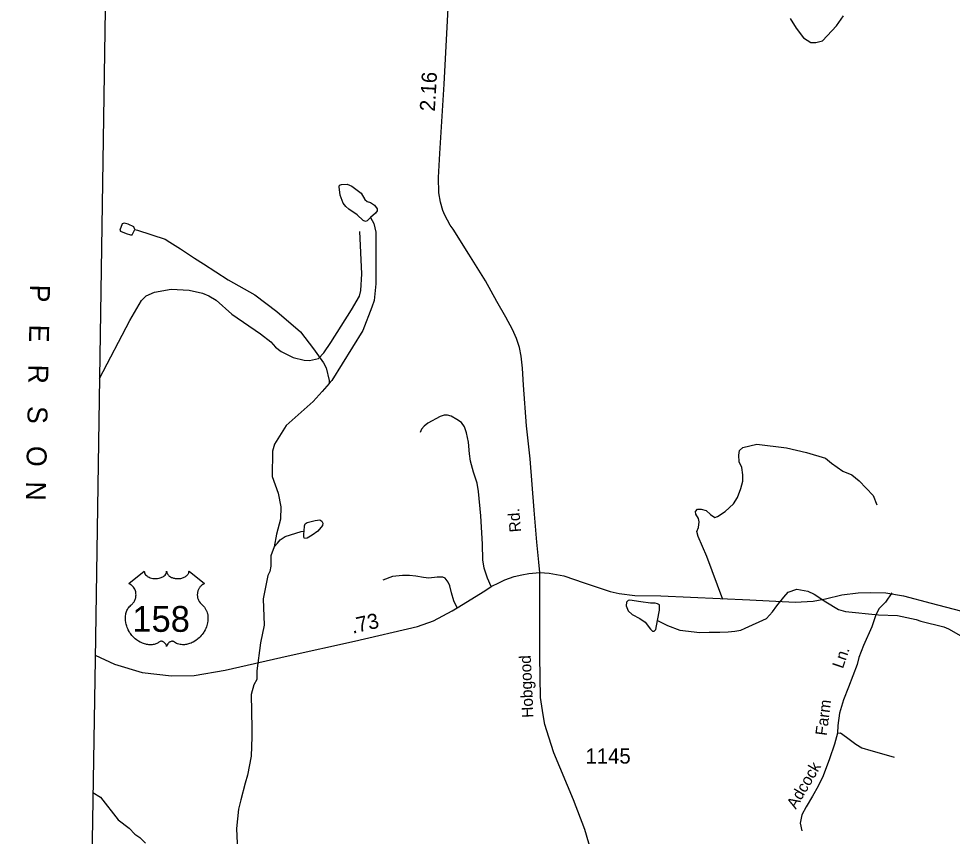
# Model space of a CAD drawing. Extents: x 2056842 to 2160602, y 826753 to 1016856.
# Drawn here: x 2058297 to 2065985, y 938922 to 945656 of the extents above; entities that cross this region are included whole.
import ezdxf

# ---------------------------------------------------------------- set-up
doc = ezdxf.new("R2010")
doc.units = 0
for name, color, linetype in [('Exist Boundary Political CountyLine', 7, 'Continuous'), ('Exist Boundary Political CountyLine Label', 7, 'Continuous'), ('Exist Hydrographic Misc Water Feature', 7, 'Continuous'), ('Exist Hydrographic River Shore', 7, 'Continuous'), ('Exist Road Non-System Type 51', 7, 'Continuous'), ('Exist Road Non-System Type 51 Label', 7, 'Continuous'), ('Exist Road Primary US Attributed', 7, 'Continuous'), ('Exist Road Primary US Mileage Hundredths English Label', 7, 'Continuous'), ('Exist Road Primary US Shield CELL', 7, 'Continuous'), ('Exist Road Primary US Shield Number Label', 7, 'Continuous'), ('Exist Road Secondary Mileage Hundredths English Label', 7, 'Continuous'), ('Exist Road Secondary Type 51 Attributed', 7, 'Continuous'), ('Exist Road Secondary Type 51 Label', 7, 'Continuous'), ('Exist Road Secondary Type 51 Number Label', 7, 'Continuous')]:
    doc.layers.add(name, color=color, linetype=linetype)

msp = doc.modelspace()

# ---------------------------------------------------------------- linework, layer by layer
at = {"layer": 'Exist Boundary Political CountyLine'}
msp.add_lwpolyline([(2059856.6, 1016190.3), (2059992.1, 1014583.5), (2060287.9, 1010619.4), (2060242.2, 1008370.9), (2060207.5, 1006770.5), (2060178.3, 1005306.3), (2060151, 1003993.9), (2060126.7, 1003051.7), (2060085.9, 1001469.5), (2060082.6, 1001042.9), (2059970.1, 996247.2), (2059900.3, 992964.9), (2059780.5, 986400.7), (2059706.7, 983126.5), (2059583, 976558.1), (2059387.4, 966719.6), (2059309.7, 963431.4), (2059197.6, 956451.1), (2059161.2, 955539), (2058926.7, 940379.5), (2058724.8, 928102.2), (2058408.1, 910016.3), (2058297.2, 904795.7)], dxfattribs=at)
at = {"layer": 'Exist Hydrographic Misc Water Feature'}
for points in [[(2061194.4, 944018.4), (2061165.4, 943989.4), (2061153.8, 943985), (2061135, 943993.7), (2061084.3, 944040.1), (2061016.2, 944088), (2060990.1, 944108.3), (2060968.4, 944137.3), (2060943.7, 944201.1), (2060936.5, 944272.1), (2060939.4, 944285.1), (2060955.3, 944290.9), (2061003.1, 944292.4), (2061040.8, 944275), (2061116.1, 944218.5), (2061148, 944167.7), (2061165.4, 944150.3), (2061192.9, 944141.6), (2061226.3, 944118.4), (2061248, 944090.9), (2061249.4, 944072), (2061234.9, 944053.2), (2061194.4, 944018.4)], [(2061194.4, 944018.4), (2061222.5, 943968.1), (2061238.5, 943896.2), (2061239.3, 943472.1), (2061223.5, 943334.1), (2061205.7, 943280.1), (2061130, 943087.9), (2060876.8, 942675.5), (2060852.8, 942651.4)], [(2059198.4, 943962.4), (2059166.4, 943970.3), (2059150.5, 943966.3), (2059130.6, 943914.2), (2059134.7, 943906.2), (2059182.6, 943886.3)], [(2059182.6, 943886.3), (2059218.7, 943874.4), (2059230.6, 943874.4), (2059254.6, 943918.5)], [(2059254.6, 943918.5), (2059244.6, 943942.5), (2059198.4, 943962.4)], [(2059254.6, 943918.5), (2059274.5, 943914.5), (2059502.7, 943839), (2059542.9, 943815), (2059629, 943761.1), (2059744.9, 943684.2), (2059819.1, 943635.5), (2060023.4, 943505.9), (2060241.5, 943382.3), (2060421.8, 943244.6), (2060618, 943077), (2060724.7, 942935.4), (2060808.5, 942821.4), (2060828.6, 942779.4), (2060852.8, 942675.4), (2060852.8, 942651.4)], [(2060852.8, 942651.4), (2060797.1, 942583.9), (2060723.2, 942502.7), (2060499.7, 942304.8), (2060403.9, 942150.6), (2060386.2, 942094.6), (2060383.3, 941884.3), (2060432.6, 941746.7), (2060454.8, 941634.7), (2060452.9, 941534.7), (2060419.3, 941410.6), (2060401.3, 941306.7)], [(2060647, 941435.7), (2060651.3, 941478.4), (2060655.7, 941494.4), (2060671.6, 941506), (2060738.3, 941521.9), (2060777.4, 941527.7), (2060793.3, 941516.1), (2060800.6, 941500.2), (2060797.7, 941481.3), (2060761.5, 941434.9), (2060715.1, 941401.6), (2060673.1, 941378.4), (2060649.9, 941375.5), (2060644.1, 941385.6), (2060645.5, 941413.2), (2060647, 941435.7)], [(2060401.3, 941306.7), (2060429.7, 941336.3), (2060451.3, 941362.7), (2060491.3, 941390.7), (2060623.1, 941433.1), (2060647, 941435.7)], [(2060401.3, 941306.7), (2060374.6, 941232), (2060373.8, 941146.6), (2060365.8, 941102.6), (2060349.8, 941070.5), (2060310.2, 940878.4), (2060318.4, 940660), (2060289.4, 940515.1), (2060259, 940283.8), (2060257.5, 940214.2), (2060232.9, 940169.3), (2060212.6, 940089.6), (2060216.1, 939808.3), (2060218.4, 939741.6), (2060212.6, 939580.7), (2060180.8, 939426.2), (2060160.9, 939358.3), (2060127.3, 939222.2), (2060108.3, 939145.8), (2060090.9, 938984.8), (2060098, 938802.2)], [(2063558.2, 940698.5), (2063638.4, 940658.6), (2063742.4, 940618.8), (2063906.6, 940599.1), (2063982.5, 940603.2), (2064070.7, 940603.4), (2064138.8, 940604.9), (2064194.5, 940611.6), (2064242.5, 940619.7), (2064278.4, 940635.8), (2064456.1, 940716.5), (2064505.4, 940770.2), (2064540.1, 940820.9), (2064598.1, 940892.4), (2064634, 940932.4), (2064705.9, 940956.5), (2064793.9, 940940.7), (2064846, 940916.9), (2064942.1, 940853), (2065048.2, 940789.2), (2065106.2, 940773.3), (2065378.3, 940745.8), (2065534.1, 940740.2), (2065686.3, 940708.4), (2065724.4, 940692.4), (2065914.3, 940646.8), (2065954.5, 940630.9), (2066092.7, 940551.1)], [(2063558.2, 940698.5), (2063574, 940783.2), (2063574, 940813.7), (2063572.6, 940828.2), (2063558.1, 940836.9), (2063539.3, 940841.2), (2063500.1, 940842.7), (2063419, 940852.8), (2063330.6, 940867.3), (2063314.7, 940864.4), (2063303.1, 940849.9), (2063298.7, 940819.5), (2063314.7, 940777.4), (2063349.4, 940749.9), (2063413.2, 940715.1), (2063455.2, 940686.1), (2063500.1, 940628.1), (2063516.1, 940610.7), (2063530.6, 940610.7), (2063543.6, 940625.2), (2063558.2, 940698.5)], [(2058908.2, 939283), (2058971.2, 939244), (2059117.6, 939056.3), (2059205.8, 938988.4), (2059253.8, 938940.6), (2059293.8, 938912.6), (2059342, 938864.7)]]:
    msp.add_lwpolyline(points, dxfattribs=at)
at = {"layer": 'Exist Hydrographic River Shore'}
msp.add_lwpolyline([(2064650.9, 945658.3), (2064699.1, 945576.2), (2064759.5, 945498.5), (2064819.4, 945458.5), (2064860.9, 945459.4), (2064916, 945473.9), (2065030.4, 945595.7), (2065088.4, 945678.3)], dxfattribs=at)
at = {"layer": 'Exist Road Non-System Type 51'}
for points in [[(2058962.5, 942692.6), (2059211.5, 943169.6), (2059309.4, 943335.7), (2059347.9, 943374.3), (2059416.1, 943403.9), (2059552.5, 943427.7), (2059700.8, 943418.8), (2059810.5, 943395), (2059863.8, 943374.3), (2059923.1, 943338.7), (2060053.6, 943223), (2060289.3, 943059.8), (2060372.4, 942994.6), (2060410.9, 942950.1), (2060458.3, 942914.5), (2060556.2, 942864), (2060648.1, 942843.3), (2060692.6, 942840.3), (2060766.7, 942858.1), (2060811.2, 942902.6), (2060867.5, 942988.6), (2061038, 943258.6), (2061103.3, 943371.3), (2061115.1, 943415.8), (2061124, 943555.2), (2061107.7, 943902.3)], [(2062187.8, 940978.4), (2062156.8, 941048), (2062129.6, 941129.7), (2062119.2, 941199.2), (2062116.9, 941327), (2062101.4, 941561.9), (2062083.1, 941762.9), (2062071.3, 941831.5), (2062043.1, 941919.8), (2062018.2, 942011), (2062010.7, 942072), (2061999.9, 942168.8), (2061985.8, 942245.8), (2061967, 942294.7), (2061944.5, 942328.5), (2061905, 942355.8), (2061859.5, 942382.1), (2061828.5, 942391.5), (2061801.2, 942391.5), (2061768.3, 942378.3), (2061666.9, 942323.8), (2061635.9, 942300.3), (2061615.2, 942275.9), (2061602, 942247.7)], [(2064095.8, 940872.3), (2063963, 941226), (2063891.1, 941391.3), (2063881.5, 941432.9), (2063895.9, 941464.9), (2063900.7, 941512.9), (2063894.3, 941538.5), (2063873.6, 941575.3), (2063870.4, 941597.7), (2063887.9, 941615.4), (2063916.7, 941615.4), (2063956.7, 941604.2), (2063995.1, 941572.1), (2064028.7, 941546.5), (2064052.7, 941554.5), (2064113.4, 941596.1), (2064182.2, 941660.2), (2064217.4, 941713), (2064244.5, 941786.6), (2064260.5, 941845.8), (2064260.5, 941898.6), (2064252.4, 941958.8), (2064230, 942005.2), (2064226.8, 942059.6), (2064233.2, 942098), (2064260.4, 942125.2), (2064375.5, 942150.8), (2064620.2, 942120.4), (2064783.3, 942082), (2064940.7, 942035.5), (2064990.3, 941995.5), (2065083, 941928.3), (2065156.6, 941899.5), (2065219, 941849.9), (2065332.5, 941729.9), (2065362.9, 941651.5)], [(2061908.3, 940803.7), (2061881.1, 940860), (2061862.3, 940926.8), (2061848.2, 940985), (2061833.6, 941015.1), (2061810.1, 941047), (2061790.4, 941056.4), (2061742.5, 941055.5), (2061675.8, 941048.9), (2061629.8, 941053.6), (2061566.8, 941063.9), (2061514.7, 941070.5), (2061456.4, 941069.6), (2061376.1, 941060.2), (2061296.2, 941031)], [(2065487.3, 940926.8), (2065434, 940850.6), (2065381.3, 940797.8), (2065354.1, 940745), (2065322.1, 940647.3), (2065253.3, 940492.1), (2065215.5, 940394.1), (2065202.7, 940336.5), (2065129.1, 940150.9), (2065087.6, 940046.9), (2065057.2, 939936.5), (2065042.8, 939834.1), (2065039.6, 939770.8)], [(2065039.6, 939770.8), (2065015.6, 939681.2), (2064974, 939559.6), (2064921.3, 939419.5), (2064879.7, 939334.7), (2064834.9, 939253.1), (2064780.6, 939163.5), (2064745.4, 939097.9), (2064731, 939029.1), (2064745.4, 938966.6)], [(2065039.6, 939770.8), (2065065.2, 939774), (2065113.1, 939737.2), (2065189.9, 939679.6), (2065239.5, 939649.2), (2065313, 939628.4), (2065401, 939602.8), (2065506.5, 939572.4)]]:
    msp.add_lwpolyline(points, dxfattribs=at)
at = {"layer": 'Exist Road Primary US Attributed'}
for points in [[(2058927.3, 940414.8), (2059086.5, 940340.3), (2059313.6, 940269.8), (2059556.6, 940244.2), (2059742.1, 940247.4), (2059998, 940289), (2060514.9, 940407.3), (2061061.8, 940528.9), (2061580.9, 940648.9), (2061712, 940695.3), (2061867.1, 940778.5), (2061908.3, 940803.7), (2062135.3, 940944.4), (2062187.8, 940978.4), (2062255.3, 941011.6), (2062301.1, 941033.1), (2062378.1, 941060.9), (2062441.1, 941075.8), (2062497.7, 941086.9), (2062588.8, 941094.7)], [(2062588.8, 941094.7), (2062627.5, 941091.6), (2062665.5, 941088.8), (2062785.4, 941066.8), (2062953.3, 941009.2), (2063167.5, 940938.8), (2063240.4, 940921.3), (2063371.5, 940905.3), (2063585.5, 940902.4), (2064318.5, 940870.4), (2064689.8, 940850.9), (2064839.5, 940858.8), (2064940.2, 940878), (2065076.1, 940910), (2065208.8, 940927.6), (2065309.6, 940930.8), (2065436.9, 940927.6), (2065582.5, 940902), (2065809.5, 940842.8), (2066494.6, 940663.7)]]:
    msp.add_lwpolyline(points, dxfattribs=at)
at = {"layer": 'Exist Road Primary US Shield CELL'}
msp.add_lwpolyline([(2059331.8, 941105.1), (2059332.1, 941099.8), (2059333.4, 941093.4), (2059334.4, 941090.2), (2059337.4, 941083.9), (2059342.2, 941076.6), (2059349, 941069.4), (2059356.7, 941063.1), (2059361.9, 941059.7), (2059370.7, 941055), (2059380.6, 941050.8), (2059391.7, 941047.6), (2059403, 941045.3), (2059415.4, 941044), (2059427.6, 941043.7), (2059440.8, 941044.7), (2059455.4, 941047.5), (2059462.2, 941049.3), (2059469.7, 941051.9), (2059476.7, 941054.8), (2059484.3, 941058.9), (2059490.5, 941062.8), (2059495.3, 941066.3), (2059502.2, 941072.9), (2059507.6, 941079.6), (2059509.9, 941083.4), (2059511.8, 941087.1), (2059514.5, 941094.8), (2059515.3, 941098.2), (2059515.8, 941105.3), (2059516.3, 941099.4), (2059516.9, 941095.6), (2059517.9, 941092), (2059519.4, 941088.1), (2059522.1, 941082.7), (2059525.2, 941078.1), (2059530.9, 941071.3), (2059534.5, 941068), (2059537.7, 941065.3), (2059546.5, 941059.3), (2059556.7, 941054.2), (2059561.7, 941052), (2059566.9, 941050.1), (2059573.4, 941048.2), (2059580.2, 941046.6), (2059586.8, 941045.4), (2059593.7, 941044.4), (2059600.7, 941043.9), (2059606.4, 941043.7), (2059613.3, 941043.8), (2059619.8, 941044.2), (2059626.4, 941045), (2059633.7, 941046.2), (2059639.5, 941047.5), (2059647.3, 941049.5), (2059654.3, 941052), (2059660.4, 941054.7), (2059668.4, 941058.9), (2059674.9, 941062.9), (2059679.6, 941066.7), (2059685.2, 941071.9), (2059690.5, 941078), (2059693.6, 941082.5), (2059695.8, 941087.1), (2059697.9, 941092), (2059699.1, 941097.2), (2059699.7, 941101.7), (2059699.9, 941105.5), (2059828.5, 941003), (2059825.4, 941001.9), (2059818.4, 940998.5), (2059812.9, 940995.2), (2059804, 940989), (2059800.3, 940985.5), (2059796.5, 940982), (2059793, 940978.2), (2059789.9, 940974.6), (2059786.2, 940969.4), (2059782.8, 940964.3), (2059779.6, 940958.6), (2059777.2, 940953.6), (2059773.2, 940943.3), (2059771.3, 940936.8), (2059770.1, 940931.2), (2059768.6, 940919.7), (2059768.2, 940914.3), (2059768.2, 940908.9), (2059768.5, 940903.2), (2059769, 940897.7), (2059770, 940892), (2059770.9, 940887), (2059772.5, 940880.8), (2059774.8, 940873.7), (2059777.6, 940866.8), (2059783.5, 940855.6), (2059791.1, 940844.2), (2059796.4, 940837.8), (2059801.8, 940832.4), (2059809.7, 940825.7), (2059814, 940821.9), (2059818.9, 940816.9), (2059827, 940807.6), (2059830.2, 940803.2), (2059833.6, 940798.2), (2059836.6, 940793.1), (2059839.6, 940787.7), (2059842.1, 940782.9), (2059846.6, 940771.9), (2059849.9, 940761.2), (2059851.4, 940755.5), (2059853.8, 940742.9), (2059854.7, 940736.7), (2059855.7, 940724.4), (2059855.7, 940709.5), (2059854.6, 940695.3), (2059851.9, 940678.9), (2059849.7, 940669), (2059846.3, 940657.5), (2059843.1, 940647.6), (2059837.2, 940632.9), (2059832, 940622.2), (2059825.2, 940609.8), (2059820.6, 940602.3), (2059815.2, 940594.2), (2059808.5, 940584.9), (2059800.6, 940575.1), (2059791.1, 940564.6), (2059783.4, 940557), (2059773.4, 940548), (2059767.3, 940543), (2059758.6, 940536.5), (2059746.8, 940528.6), (2059735.1, 940521.8), (2059725.1, 940516.7), (2059716.3, 940512.9), (2059704.9, 940508.6), (2059686, 940503.3), (2059679, 940501.9), (2059670.8, 940500.7), (2059663.2, 940499.9), (2059655.7, 940499.5), (2059645.7, 940499.5), (2059635.8, 940500.2), (2059626.3, 940501.6), (2059616.5, 940503.6), (2059606.3, 940506.7), (2059597, 940510.3), (2059587.6, 940515), (2059571.6, 940525), (2059567.1, 940527.4), (2059564.5, 940528.1), (2059558.3, 940528.4), (2059552.5, 940527.2), (2059546.6, 940524.8), (2059543.1, 940522.9), (2059538.3, 940519.8), (2059534.7, 940516.9), (2059530.3, 940512.8), (2059527.2, 940509.3), (2059524.9, 940506.5), (2059520.4, 940499.5), (2059518.8, 940496.1), (2059517.2, 940491.8), (2059515.7, 940485.4), (2059513.7, 940493.4), (2059511.3, 940498.8), (2059508.6, 940503.3), (2059505.7, 940507.4), (2059501.2, 940512.5), (2059497.2, 940516.4), (2059492.4, 940520.3), (2059487.2, 940523.5), (2059483.1, 940525.6), (2059479.3, 940527), (2059474.6, 940528.2), (2059470.8, 940528.5), (2059467.7, 940528.4), (2059463.4, 940527.4), (2059457.6, 940523.2), (2059452.1, 940519.4), (2059446.1, 940515.7), (2059439, 940511.9), (2059433.7, 940509.5), (2059427.5, 940507.1), (2059420.2, 940504.6), (2059412.3, 940502.6), (2059404.2, 940501), (2059397, 940499.8), (2059389.4, 940499.1), (2059382.5, 940498.9), (2059375.3, 940499), (2059368.5, 940499.5), (2059360.7, 940500.2), (2059350.9, 940501.7), (2059342.9, 940503.5), (2059334.4, 940505.8), (2059325.7, 940508.5), (2059316.3, 940512.1), (2059304.6, 940517.2), (2059296.5, 940521.3), (2059283.7, 940528.7), (2059268.6, 940539.1), (2059257.3, 940548.3), (2059249, 940555.8), (2059236.7, 940568.3), (2059229.5, 940576.4), (2059218.3, 940591), (2059211.1, 940601.6), (2059206.4, 940609.3), (2059199.5, 940621.8), (2059195.8, 940629.6), (2059190.9, 940641), (2059187.1, 940651.4), (2059183.9, 940661.3), (2059182.2, 940667.6), (2059179.8, 940678.6), (2059178.3, 940686.5), (2059176.8, 940697.2), (2059176, 940708.5), (2059175.9, 940718.9), (2059176.2, 940727.6), (2059177.1, 940737.7), (2059178.9, 940748.4), (2059180.9, 940757.6), (2059182.8, 940764.2), (2059185.5, 940772.2), (2059189.1, 940781.1), (2059193.4, 940789.6), (2059197.4, 940796.7), (2059202.5, 940804.3), (2059207.5, 940810.8), (2059214.1, 940817.9), (2059220.9, 940824.4), (2059227.2, 940829.5), (2059234.6, 940836.8), (2059238.5, 940841.2), (2059243.2, 940847.4), (2059246.9, 940853.1), (2059249.9, 940858.2), (2059253.8, 940865.7), (2059256.1, 940871.3), (2059259.1, 940880), (2059260.6, 940886.1), (2059262.1, 940893.9), (2059263.1, 940901.3), (2059263.5, 940910.5), (2059263.2, 940918.1), (2059262.2, 940927), (2059260.6, 940935.5), (2059258.6, 940942.9), (2059255.4, 940951.4), (2059252.4, 940957.7), (2059247.5, 940966.1), (2059242, 940973.9), (2059236.4, 940980.3), (2059230.7, 940986), (2059225.2, 940990.3), (2059220, 940994), (2059213.5, 940997.9), (2059207.2, 941001), (2059203.2, 941002.6)], close=True, dxfattribs=at)
at = {"layer": 'Exist Road Secondary Type 51 Attributed'}
for points in [[(2062588.8, 941094.7), (2062580.3, 941179.5), (2062562.8, 941345), (2062541.3, 941609), (2062508.8, 942030.1), (2062478.1, 942302.1), (2062455.1, 942638.5), (2062446.7, 942777.6), (2062434.7, 942874.9), (2062420.7, 942946.3), (2062395.7, 943020.5), (2062364.2, 943096.6), (2062308.5, 943198.6), (2062234.4, 943327.5), (2062141.6, 943495.4), (2062002.5, 943715.2), (2061874.8, 943922.1), (2061850.5, 943955.4), (2061805, 944037), (2061790.2, 944075.9), (2061770.9, 944144.5), (2061758.1, 944221.3), (2061754, 944348.6), (2061766.1, 944545), (2061799.6, 945115.2), (2061834.8, 945743)], [(2063273.2, 936830), (2063135.8, 936971.2), (2063008.7, 937167.2), (2062939.9, 937324), (2062903.2, 937492.1), (2062905.5, 937628.8), (2062909.9, 937734.9), (2062957.8, 938080.5), (2063008.2, 938422.1), (2063019.4, 938524.5), (2063022.6, 938711.7), (2063009.8, 938799.7), (2062959.4, 938978.2), (2062866.7, 939223), (2062702.8, 939609.4), (2062662.8, 939737.4), (2062630.8, 939841.4), (2062614.8, 939921.4), (2062594, 940064.7), (2062589.2, 940402.3), (2062588, 940837.9), (2062588, 940957.1), (2062588.8, 941094.7)]]:
    msp.add_lwpolyline(points, dxfattribs=at)

# ---------------------------------------------------------------- texts
at = {"layer": 'Exist Boundary Political CountyLine Label'}
msp.add_text('P   E   R   S   O  N', height=164.042, rotation=268.86102, dxfattribs=at).set_placement((2058391.5, 943466.7))
at = {"layer": 'Exist Road Non-System Type 51 Label'}
for s, rotation, p in [('Ln.', 71.0264, (2065083.3, 940297.4)), ('Farm', 82.75738, (2064950.3, 939747.1)), ('Adcock', 59.54128, (2064696.3, 939140.1))]:
    msp.add_text(s, height=95, rotation=rotation, dxfattribs=at).set_placement(p)
at = {"layer": 'Exist Road Primary US Mileage Hundredths English Label'}
msp.add_text('.73', height=125, rotation=13.01351, dxfattribs=at).set_placement((2061047.2, 940589.7))
at = {"layer": 'Exist Road Primary US Shield Number Label'}
msp.add_text('158', height=212.5, dxfattribs=at).set_placement((2059233, 940605.8))
at = {"layer": 'Exist Road Secondary Mileage Hundredths English Label'}
msp.add_text('2.16', height=125, rotation=86.62949, dxfattribs=at).set_placement((2061723.7, 944889.4))
at = {"layer": 'Exist Road Secondary Type 51 Label'}
for s, rotation, p in [('Rd.', 94.59318, (2062434.7, 941429.5)), ('Hobgood', 92.53712, (2062536.5, 939899.8))]:
    msp.add_text(s, height=95, rotation=rotation, dxfattribs=at).set_placement(p)
at = {"layer": 'Exist Road Secondary Type 51 Number Label'}
msp.add_text('1145', height=125, dxfattribs=at).set_placement((2062964.8, 939520.5))

doc.saveas('drawing.dxf')
